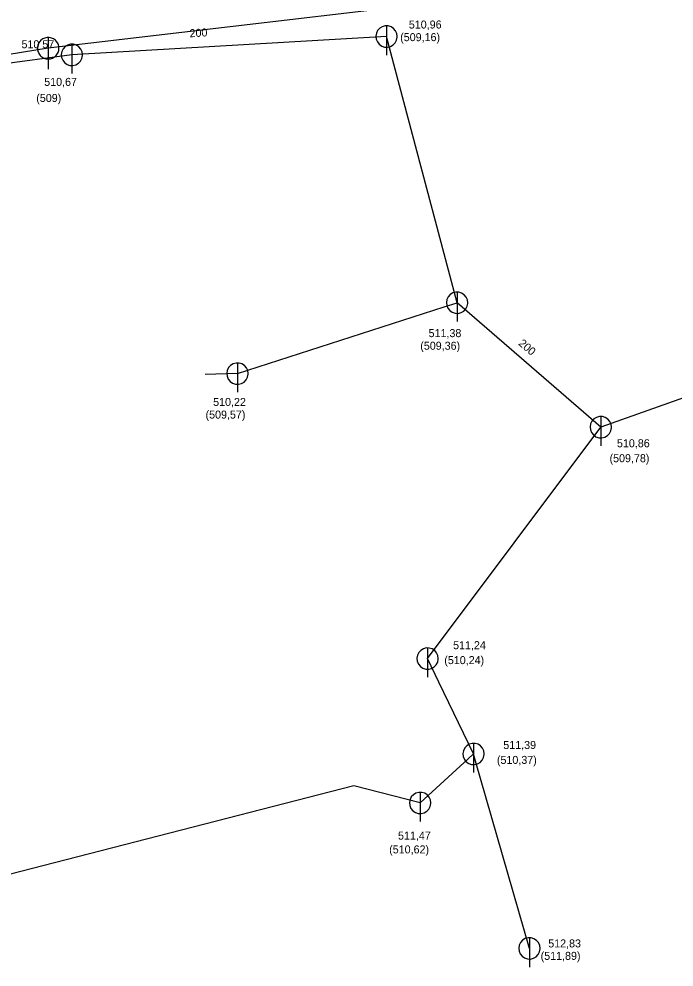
# Model space of a CAD drawing. Extents: x -476058 to -471893, y -1155786 to -1152000.
# Drawn here: x -474993.4 to -474932.1, y -1154255.9 to -1154167.1 of the extents above; entities that cross this region are included whole.
import ezdxf

# ---------------------------------------------------------------- set-up
doc = ezdxf.new("R2010")
doc.units = 0
for name, color, linetype in [('Vrstva 1', 7, 'Continuous'), ('Vrstva 10', 7, 'Continuous'), ('Vrstva 18', 7, 'Continuous'), ('Vrstva 3', 7, 'Continuous'), ('Vrstva 35', 7, 'Continuous'), ('Vrstva 4', 7, 'Continuous'), ('Vrstva 45', 7, 'Continuous'), ('Vrstva 50', 7, 'Continuous'), ('Vrstva 51', 7, 'Continuous')]:
    doc.layers.add(name, color=color, linetype=linetype)

msp = doc.modelspace()

# ---------------------------------------------------------------- linework, layer by layer
at = {"layer": 'Vrstva 1'}
msp.add_line((-474990.69, -1154169.83), (-474990.69, -1154169.83), dxfattribs=at)
at = {"layer": 'Vrstva 10'}
for p, q in [((-474959.01, -1154167.73), (-474959.01, -1154170.478)), ((-474988.47, -1154169.45), (-474988.47, -1154172.198)), ((-474952.4, -1154192.68), (-474952.4, -1154195.428)), ((-474972.97, -1154199.32), (-474972.97, -1154202.068)), ((-474938.95, -1154204.34), (-474938.95, -1154207.088)), ((-474955.16, -1154226.02), (-474955.16, -1154228.768)), ((-474950.86, -1154234.96), (-474950.86, -1154237.708)), ((-474955.859, -1154239.55), (-474955.859, -1154242.298)), ((-474945.626, -1154253.18), (-474945.626, -1154255.928))]:
    msp.add_line(p, q, dxfattribs=at)
for points in [[(-474958.01, -1154168.73), (-474958.049, -1154168.451), (-474958.166, -1154168.194), (-474958.349, -1154167.979), (-474958.585, -1154167.825), (-474958.855, -1154167.742), (-474959.137, -1154167.738), (-474959.409, -1154167.813), (-474959.649, -1154167.961), (-474959.839, -1154168.17), (-474959.962, -1154168.424), (-474960.01, -1154168.702), (-474959.978, -1154168.983), (-474959.869, -1154169.243), (-474959.691, -1154169.462), (-474959.46, -1154169.624), (-474959.192, -1154169.714), (-474958.91, -1154169.726), (-474958.636, -1154169.658), (-474958.392, -1154169.517), (-474958.197, -1154169.313), (-474958.067, -1154169.063), (-474958.011, -1154168.786), (-474958.01, -1154168.73)], [(-474989.682, -1154169.83), (-474989.688, -1154169.725), (-474989.704, -1154169.621), (-474989.732, -1154169.519), (-474989.77, -1154169.42), (-474989.817, -1154169.326), (-474989.875, -1154169.238), (-474989.941, -1154169.156), (-474990.016, -1154169.081), (-474990.098, -1154169.015), (-474990.186, -1154168.957), (-474990.28, -1154168.91), (-474990.379, -1154168.872), (-474990.481, -1154168.844), (-474990.585, -1154168.828), (-474990.69, -1154168.822), (-474990.795, -1154168.828), (-474990.9, -1154168.844), (-474991.002, -1154168.872), (-474991.1, -1154168.91), (-474991.194, -1154168.957), (-474991.283, -1154169.015), (-474991.365, -1154169.081), (-474991.439, -1154169.156), (-474991.505, -1154169.238), (-474991.563, -1154169.326), (-474991.611, -1154169.42), (-474991.649, -1154169.519), (-474991.676, -1154169.621), (-474991.692, -1154169.725), (-474991.698, -1154169.83), (-474991.692, -1154169.935), (-474991.676, -1154170.04), (-474991.649, -1154170.142), (-474991.611, -1154170.24), (-474991.563, -1154170.334), (-474991.505, -1154170.423), (-474991.439, -1154170.505), (-474991.365, -1154170.579), (-474991.283, -1154170.645), (-474991.194, -1154170.703), (-474991.1, -1154170.751), (-474991.002, -1154170.789), (-474990.9, -1154170.816), (-474990.795, -1154170.832), (-474990.69, -1154170.838), (-474990.585, -1154170.832), (-474990.481, -1154170.816), (-474990.379, -1154170.789), (-474990.28, -1154170.751), (-474990.186, -1154170.703), (-474990.098, -1154170.645), (-474990.016, -1154170.579), (-474989.941, -1154170.505), (-474989.875, -1154170.423), (-474989.817, -1154170.334), (-474989.77, -1154170.24), (-474989.732, -1154170.142), (-474989.704, -1154170.04), (-474989.688, -1154169.935), (-474989.682, -1154169.83)], [(-474990.69, -1154168.822), (-474990.69, -1154171.798)], [(-474987.47, -1154170.45), (-474987.509, -1154170.171), (-474987.626, -1154169.914), (-474987.809, -1154169.699), (-474988.045, -1154169.545), (-474988.315, -1154169.462), (-474988.597, -1154169.458), (-474988.869, -1154169.533), (-474989.109, -1154169.681), (-474989.299, -1154169.89), (-474989.422, -1154170.144), (-474989.47, -1154170.422), (-474989.438, -1154170.703), (-474989.329, -1154170.963), (-474989.151, -1154171.182), (-474988.92, -1154171.344), (-474988.652, -1154171.434), (-474988.37, -1154171.446), (-474988.096, -1154171.378), (-474987.852, -1154171.237), (-474987.657, -1154171.033), (-474987.527, -1154170.783), (-474987.471, -1154170.506), (-474987.47, -1154170.45)], [(-474951.4, -1154193.68), (-474951.439, -1154193.401), (-474951.556, -1154193.144), (-474951.739, -1154192.929), (-474951.975, -1154192.775), (-474952.245, -1154192.692), (-474952.527, -1154192.688), (-474952.799, -1154192.763), (-474953.039, -1154192.911), (-474953.229, -1154193.12), (-474953.352, -1154193.374), (-474953.4, -1154193.652), (-474953.368, -1154193.933), (-474953.259, -1154194.193), (-474953.081, -1154194.412), (-474952.85, -1154194.574), (-474952.582, -1154194.664), (-474952.3, -1154194.676), (-474952.026, -1154194.608), (-474951.782, -1154194.467), (-474951.587, -1154194.263), (-474951.457, -1154194.013), (-474951.401, -1154193.736), (-474951.4, -1154193.68)], [(-474971.97, -1154200.32), (-474972.009, -1154200.041), (-474972.126, -1154199.784), (-474972.309, -1154199.569), (-474972.545, -1154199.415), (-474972.815, -1154199.332), (-474973.097, -1154199.328), (-474973.369, -1154199.403), (-474973.609, -1154199.551), (-474973.799, -1154199.76), (-474973.922, -1154200.014), (-474973.97, -1154200.292), (-474973.938, -1154200.573), (-474973.829, -1154200.833), (-474973.651, -1154201.052), (-474973.42, -1154201.214), (-474973.152, -1154201.304), (-474972.87, -1154201.316), (-474972.596, -1154201.248), (-474972.352, -1154201.107), (-474972.157, -1154200.903), (-474972.027, -1154200.653), (-474971.971, -1154200.376), (-474971.97, -1154200.32)], [(-474937.95, -1154205.34), (-474937.989, -1154205.061), (-474938.106, -1154204.804), (-474938.289, -1154204.589), (-474938.525, -1154204.435), (-474938.795, -1154204.352), (-474939.077, -1154204.348), (-474939.349, -1154204.423), (-474939.589, -1154204.571), (-474939.779, -1154204.78), (-474939.902, -1154205.034), (-474939.95, -1154205.312), (-474939.918, -1154205.593), (-474939.809, -1154205.853), (-474939.631, -1154206.072), (-474939.4, -1154206.234), (-474939.132, -1154206.324), (-474938.85, -1154206.336), (-474938.576, -1154206.268), (-474938.332, -1154206.127), (-474938.137, -1154205.923), (-474938.007, -1154205.673), (-474937.951, -1154205.396), (-474937.95, -1154205.34)], [(-474954.16, -1154227.02), (-474954.199, -1154226.741), (-474954.316, -1154226.484), (-474954.499, -1154226.269), (-474954.735, -1154226.115), (-474955.005, -1154226.032), (-474955.287, -1154226.028), (-474955.559, -1154226.103), (-474955.799, -1154226.251), (-474955.989, -1154226.46), (-474956.112, -1154226.714), (-474956.16, -1154226.992), (-474956.128, -1154227.273), (-474956.019, -1154227.533), (-474955.841, -1154227.752), (-474955.61, -1154227.914), (-474955.342, -1154228.004), (-474955.06, -1154228.016), (-474954.786, -1154227.948), (-474954.542, -1154227.807), (-474954.347, -1154227.603), (-474954.217, -1154227.353), (-474954.161, -1154227.076), (-474954.16, -1154227.02)], [(-474949.86, -1154235.96), (-474949.899, -1154235.681), (-474950.016, -1154235.424), (-474950.199, -1154235.209), (-474950.435, -1154235.055), (-474950.705, -1154234.972), (-474950.987, -1154234.968), (-474951.259, -1154235.043), (-474951.499, -1154235.191), (-474951.689, -1154235.4), (-474951.812, -1154235.654), (-474951.86, -1154235.932), (-474951.828, -1154236.213), (-474951.719, -1154236.473), (-474951.541, -1154236.692), (-474951.31, -1154236.854), (-474951.042, -1154236.944), (-474950.76, -1154236.956), (-474950.486, -1154236.888), (-474950.242, -1154236.747), (-474950.047, -1154236.543), (-474949.917, -1154236.293), (-474949.861, -1154236.016), (-474949.86, -1154235.96)], [(-474954.859, -1154240.55), (-474954.898, -1154240.271), (-474955.015, -1154240.014), (-474955.198, -1154239.799), (-474955.434, -1154239.645), (-474955.704, -1154239.562), (-474955.986, -1154239.558), (-474956.258, -1154239.633), (-474956.498, -1154239.781), (-474956.688, -1154239.99), (-474956.811, -1154240.244), (-474956.859, -1154240.522), (-474956.827, -1154240.803), (-474956.718, -1154241.063), (-474956.54, -1154241.282), (-474956.309, -1154241.444), (-474956.041, -1154241.534), (-474955.759, -1154241.546), (-474955.485, -1154241.478), (-474955.241, -1154241.337), (-474955.046, -1154241.133), (-474954.916, -1154240.883), (-474954.86, -1154240.606), (-474954.859, -1154240.55)], [(-474944.626, -1154254.18), (-474944.665, -1154253.901), (-474944.782, -1154253.644), (-474944.965, -1154253.429), (-474945.201, -1154253.275), (-474945.471, -1154253.192), (-474945.753, -1154253.188), (-474946.025, -1154253.263), (-474946.265, -1154253.411), (-474946.455, -1154253.62), (-474946.578, -1154253.874), (-474946.626, -1154254.152), (-474946.594, -1154254.433), (-474946.485, -1154254.693), (-474946.307, -1154254.912), (-474946.076, -1154255.074), (-474945.808, -1154255.164), (-474945.526, -1154255.176), (-474945.252, -1154255.108), (-474945.008, -1154254.967), (-474944.813, -1154254.763), (-474944.683, -1154254.513), (-474944.627, -1154254.236), (-474944.626, -1154254.18)]]:
    msp.add_lwpolyline(points, dxfattribs=at)
at = {"layer": 'Vrstva 35'}
msp.add_lwpolyline([(-474850.38, -1154154.67), (-474890.71, -1154158.68), (-474940.09, -1154163.87), (-474990.69, -1154169.83), (-475017.24, -1154174.14), (-475043.32, -1154186.7), (-475043.59, -1154187.73)], dxfattribs=at)
at = {"layer": 'Vrstva 45'}
msp.add_line((-474988.47, -1154170.45), (-475007.973, -1154173.048), dxfattribs=at)
for points in [[(-474959.01, -1154168.73), (-474988.47, -1154170.45)], [(-474952.4, -1154193.68), (-474959.01, -1154168.73)], [(-474938.95, -1154205.34), (-474952.4, -1154193.68)], [(-474909.62, -1154194.94), (-474938.95, -1154205.34)], [(-474955.16, -1154227.02), (-474938.95, -1154205.34)], [(-474954.098, -1154229.227), (-474955.16, -1154227.02)], [(-474950.86, -1154235.96), (-474954.098, -1154229.227)]]:
    msp.add_lwpolyline(points, dxfattribs=at)
at = {"layer": 'Vrstva 50'}
for p, q in [((-474962.057, -1154238.955), (-474998.4, -1154248.28)), ((-474955.859, -1154240.55), (-474962.057, -1154238.955))]:
    msp.add_line(p, q, dxfattribs=at)
for points in [[(-474953.621, -1154194.074), (-474952.4, -1154193.68)], [(-474972.97, -1154200.32), (-474953.621, -1154194.074)], [(-474955.859, -1154240.55), (-474951.369, -1154236.427), (-474950.86, -1154235.96)], [(-474945.626, -1154254.18), (-474950.669, -1154236.624), (-474950.86, -1154235.96)]]:
    msp.add_lwpolyline(points, dxfattribs=at)
at = {"layer": 'Vrstva 51'}
msp.add_lwpolyline([(-474972.97, -1154200.32), (-474975.988, -1154200.396)], dxfattribs=at)

# ---------------------------------------------------------------- texts
at = {"layer": 'Vrstva 18'}
for rotation, p in [(3.34138, (-474977.434, -1154168.808)), (319.07751, (-474946.709, -1154197.58))]:
    msp.add_text('200 ', height=0.75, rotation=rotation, dxfattribs=at).set_placement(p)
at = {"layer": 'Vrstva 3'}
for s, p in [('510,96', (-474956.922, -1154167.983)), ('510 57 ', (-474993.19, -1154169.83)), ('510,67', (-474991.064, -1154173.358)), ('511,38', (-474955.07, -1154196.902)), ('510,22', (-474975.246, -1154203.352)), ('510,86', (-474937.432, -1154207.222)), ('511,24', (-474952.776, -1154226.143)), ('511,39', (-474948.076, -1154235.496)), ('511,47', (-474957.934, -1154243.989)), ('512,83', (-474943.868, -1154254.09))]:
    msp.add_text(s, height=0.75, dxfattribs=at).set_placement(p)
at = {"layer": 'Vrstva 4'}
for s, p in [('(509,16)', (-474957.73, -1154169.166)), ('(509)', (-474991.808, -1154174.864)), ('(509,36)', (-474955.851, -1154198.083)), ('(509,57)', (-474975.957, -1154204.535)), ('(509,78)', (-474938.127, -1154208.621)), ('(510,24)', (-474953.603, -1154227.541)), ('(510,37)', (-474948.674, -1154236.894)), ('(510,62)', (-474958.762, -1154245.28)), ('(511,89)', (-474944.58, -1154255.254))]:
    msp.add_text(s, height=0.75, dxfattribs=at).set_placement(p)

doc.saveas('drawing.dxf')
